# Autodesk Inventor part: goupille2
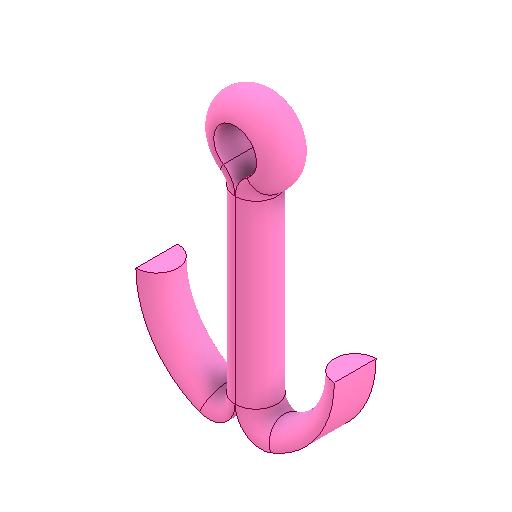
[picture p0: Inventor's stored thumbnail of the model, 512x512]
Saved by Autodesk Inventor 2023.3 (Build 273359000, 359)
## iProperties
Created: 2024-11
Part Number: goupille2
Material: Générique
Description: STEP AP203
Document SubType Name: Modeling
Designer: Thier
Density: 1 g/cm^3
Appearance: Rose
Sending System: SolidWorks 2017
Preprocessor: SwSTEP 2.0
Title: goupille2.STEP
Revision Number: ANY
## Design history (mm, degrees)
feature "Base-Balayage"
node "Solide1"
